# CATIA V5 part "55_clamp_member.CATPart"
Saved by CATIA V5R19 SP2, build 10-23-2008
Part number: 55_clamp_member
Bounding box of the stored display mesh (mm): x -69.981 to 69.981, y 70.381 to 210.342, z 14.876 to 53.376
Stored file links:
  C:\Documents and Settings\anizard\Bureau\13\55_clamp_member.CATPart
  C:\Documents and Settings\anizard\Bureau\13\anizard.CATProduct
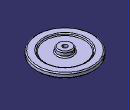
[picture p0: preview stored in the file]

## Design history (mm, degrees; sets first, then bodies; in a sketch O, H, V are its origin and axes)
Set1
  Line1: linked copy from another document
  Point1: linked copy from another document
  Point2: linked copy from another document
  Plane1: linked copy from another document
  Point3: linked copy from another document
  Point4: linked copy from another document
  Plane2 to Plane4: linked copy from another document
Body1 (main body)
  Sketch1 on yz-plane, origin (0, 0, 0), H (0, 1, 0), V (0, 0, 1)
    line L1 (146.1119, 53.3755) -> (157.8619, 53.3755)
    line L2 (157.8619, 53.3755) -> (157.8619, 41.3755)
    line L3 (157.8619, 41.3755) -> (191.3619, 41.3755)
    line L4 (191.3619, 41.3755) -> (191.3619, 44.6255)
    line L5 (191.3619, 44.6255) -> (210.3619, 44.6255)
    line L6 (210.3619, 44.6255) -> (210.3619, 32.6255)
    line L7 (210.3619, 32.6255) -> (191.3619, 32.6255)
    point P8 (191.3619, 32.6255)
    line L8 (191.3619, 32.6255) -> (191.3619, 35.8755)
    line L9 (191.3619, 35.8755) -> (160.6119, 35.8755)
    line L10 (160.6119, 35.8755) -> (160.3619, 14.8755)
    line L11 (160.3619, 14.8755) -> (156.3619, 14.8755)
    line L12 (156.3619, 14.8755) -> (156.3619, 37.8755)
    line L13 (156.3619, 37.8755) -> (154.8619, 37.8755)
    line L14 (154.8619, 37.8755) -> (154.8619, 40.8755)
    line L15 (154.8619, 40.8755) -> (146.1119, 40.8755)
    line L16 (146.1119, 40.8755) -> (146.1119, 53.3755)
    point P15 (160.3619, 14.8755)
    point P16 (160.3619, 14.8755)
    point P17 (160.6119, 35.8755)
    point P18 (160.6119, 35.8755)
    axis line L17 (163.3406, 38.6255) -> (222.7734, 38.6255)
    reference projected point E1 (156.3619, 40.8755) from Point2
    reference projected point E2 (146.1119, 40.8755) from Point3
    reference projected line E3 (140.3619, -281.1245) -> (140.3619, 98.8755) from Line1
    reference projected line E4 (140.3619, -281.1245) -> (140.3619, 98.8755) from Line1
    reference intersected line E5 through (0, 53.3755) direction (-1, 0) from Plane2
    reference intersected line E6 through (0, 40.8755) direction (-1, 0) from Plane3
    reference intersected line E7 through (0, 37.8755) direction (-1, 0) from Plane1
    reference intersected line E8 through (0, 40.8755) direction (-1, 0) from Plane3
    distance L13 L11 = 23
    distance L5 L7 = 12
    distance L3 L9 = 5.5
    distance L12 P15 = 4
    distance L12 P17 = 4.25
    distance L14 L12 = 1.5
    distance L14 L2 = 3
    distance L6 E3 = 70
    distance L8 E4 = 51
    distance L17 E8 = 2.25
    horizontal: L1 H, L3 H, L5 H, L7 H, L9 H, L11 H, L13 H, L15 H, L17 H
    vertical: L2 V, L4 V, L6 V, L8 V, L12 V, L14 V, L16 V
    coincidence: P8 L4, P16 P15, P17 P18, L12 E1, L16 E2, L1 E5, L15 E6, L13 E7
    symmetry: L3 L9 L17, L5 L7 L17
  Shaft1: profile Sketch1, axis Line1, angle 360
  Fillet1: radius 2.5, on face of Shaft1 from Sketch1.L2; face of Shaft1 from Sketch1.L4; face of Shaft1 from Sketch1.L6; face of Shaft1 from Sketch1.L10; edge [face of Shaft1 from Sketch1.L15 | face of Shaft1 from Sketch1.L14]
  Sketch2 on yz-plane, origin (0, 0, 0), H (0, 1, 0), V (0, 0, 1)
    line L1 (124.3619, 19.8755) -> (123.5119, 19.8755)
    line L2 (123.5119, 19.8755) -> (123.5119, 18.5755)
    line L3 (123.5119, 18.5755) -> (124.3619, 18.5755)
    line L4 (124.3619, 18.5755) -> (124.3619, 19.8755)
    reference projected line E1 (140.3619, -190) -> (140.3619, 190) from Line1
    reference projected line E2 (140.3619, -190) -> (140.3619, 190) from Line1
    reference intersected line E3 through (0, 19.8755) direction (-1, 0) from Plane4
    distance E2 L2 = 16.85
    distance L3 L1 = 1.3
    distance L4 E1 = 16
    horizontal: L1 H, L3 H
    vertical: L2 V, L4 V
    coincidence: L1 E3
  Groove1: profile Sketch2, axis Line1, angle 360
  Plane5: type OffsetPt, RefPlane zx-plane, RefPoint Point1
  Sketch3 on Plane5, origin (0, 140.3619, 0), H (-1, 0, 0), V (0, 0, 1)
    circle A1 centre (0, 49.1255) radius 2
    point P1 (0, 49.1255)
    reference projected point E1 (0, 49.1255) from Point4
    radius A1 = 2
    coincidence: P1 V, P1 E1
  Pocket1: profile Sketch3, direction (0, -1, 0), length 20, opposite side length 20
